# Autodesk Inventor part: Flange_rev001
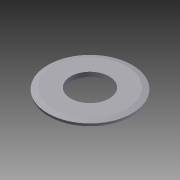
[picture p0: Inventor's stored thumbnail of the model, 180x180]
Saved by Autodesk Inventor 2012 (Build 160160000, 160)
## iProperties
Created: 2011-12
Part Number: Flange_rev001
Document SubType Name: Modeling
Designer: Alex
Density: 2.71 g/cm^3
Material: Aluminum-6061
Mass: 1.78461 g
Surface Area: 10.8756 cm^2
Volume: 0.658527 cm^3
Author: Alex
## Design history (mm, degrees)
sketch "Sketch1"
  geometry: L1 (6.35, 0)-(12.167, 0); L2 (12.167, 0)-(13.894, -0.495); L3 (6.35, -1.472)-(6.35, 0); L4 (13.894, -0.495)-(13.614, -1.472); L5 (0, -1.766)-(0, 0.294) reference; L6 (13.614, -1.472)-(6.35, -1.472); 1 further point
  constraints: 10 end point, 3 perpendicular, 1 horizontal, 1 point on line
  dimensions: "d0" = 6.35 distance from line of L3 point (0, 0); "d1" = 12.1666 distance of L1.end point (0, 0); "d2" = 164 deg angle of L2 L1; "d10" = 1.7272 horizontal distance of L2.end L1.end; "d11" = 1.016 distance of L2.end L4.end; "d12" = 13.8938 distance from line of L2.end L5 (derived)
revolve "Revolution1" sketch "Sketch1" stored, may be unused: angle "d8" = 90 deg
body "Solid1"
